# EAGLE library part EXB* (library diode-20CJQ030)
Panasonic EXBA,EXBD,EXBE Chip Resistor Networks
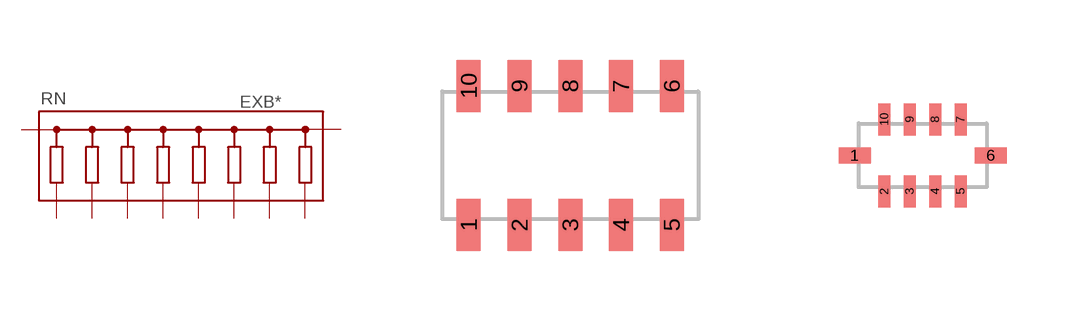
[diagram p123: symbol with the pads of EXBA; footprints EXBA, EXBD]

Designator prefix RN

## EXBA  [EXBA]
1  POL  pas
2  1  pas
3  2  pas
4  3  pas
5  4  pas
6  POL  pas
7  5  pas
8  6  pas
9  7  pas
10  8  pas

## EXBD  [EXBD]
Pads as for EXBA

## EXBE  [EXBE]
Pads as for EXBA

## Footprint EXBA (pad centres in mm)
smd 0.6 x 1.3: 1 -2.54,-1.74; 2 -1.27,-1.74; 3 0,-1.74; 4 1.27,-1.74; 5 2.54,-1.74; 6 2.54,1.74; 7 1.27,1.74; 8 0,1.74; 9 -1.27,1.74; 10 -2.54,1.74

## Footprint EXBD (pad centres in mm)
smd 0.8 x 0.4: 1 -1.7,0; 6 1.7,0
smd 0.3 x 0.8: 2 -0.953,-0.902; 3 -0.318,-0.902; 4 0.318,-0.902; 5 0.953,-0.902; 7 0.953,0.902; 8 0.318,0.902; 9 -0.318,0.902; 10 -0.953,0.902

## Footprint EXBE (pad centres in mm)
smd 1 x 0.5: 1 -2.2,0; 6 2.2,0
smd 0.4 x 1: 2 -1.2,-1.2; 3 -0.4,-1.2; 4 0.4,-1.2; 5 1.2,-1.2; 7 1.2,1.2; 8 0.4,1.2; 9 -0.4,1.2; 10 -1.2,1.2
